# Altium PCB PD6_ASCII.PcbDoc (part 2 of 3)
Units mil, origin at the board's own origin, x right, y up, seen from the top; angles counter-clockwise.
Board outline 8543.31 x 5314.96 mil, 4 copper layers (Top Layer, VBAT Plane, GND Plane, Bottom Layer), stack 62.8 mil thick; 258 components, 142 nets, 690 pads, 87 vias.
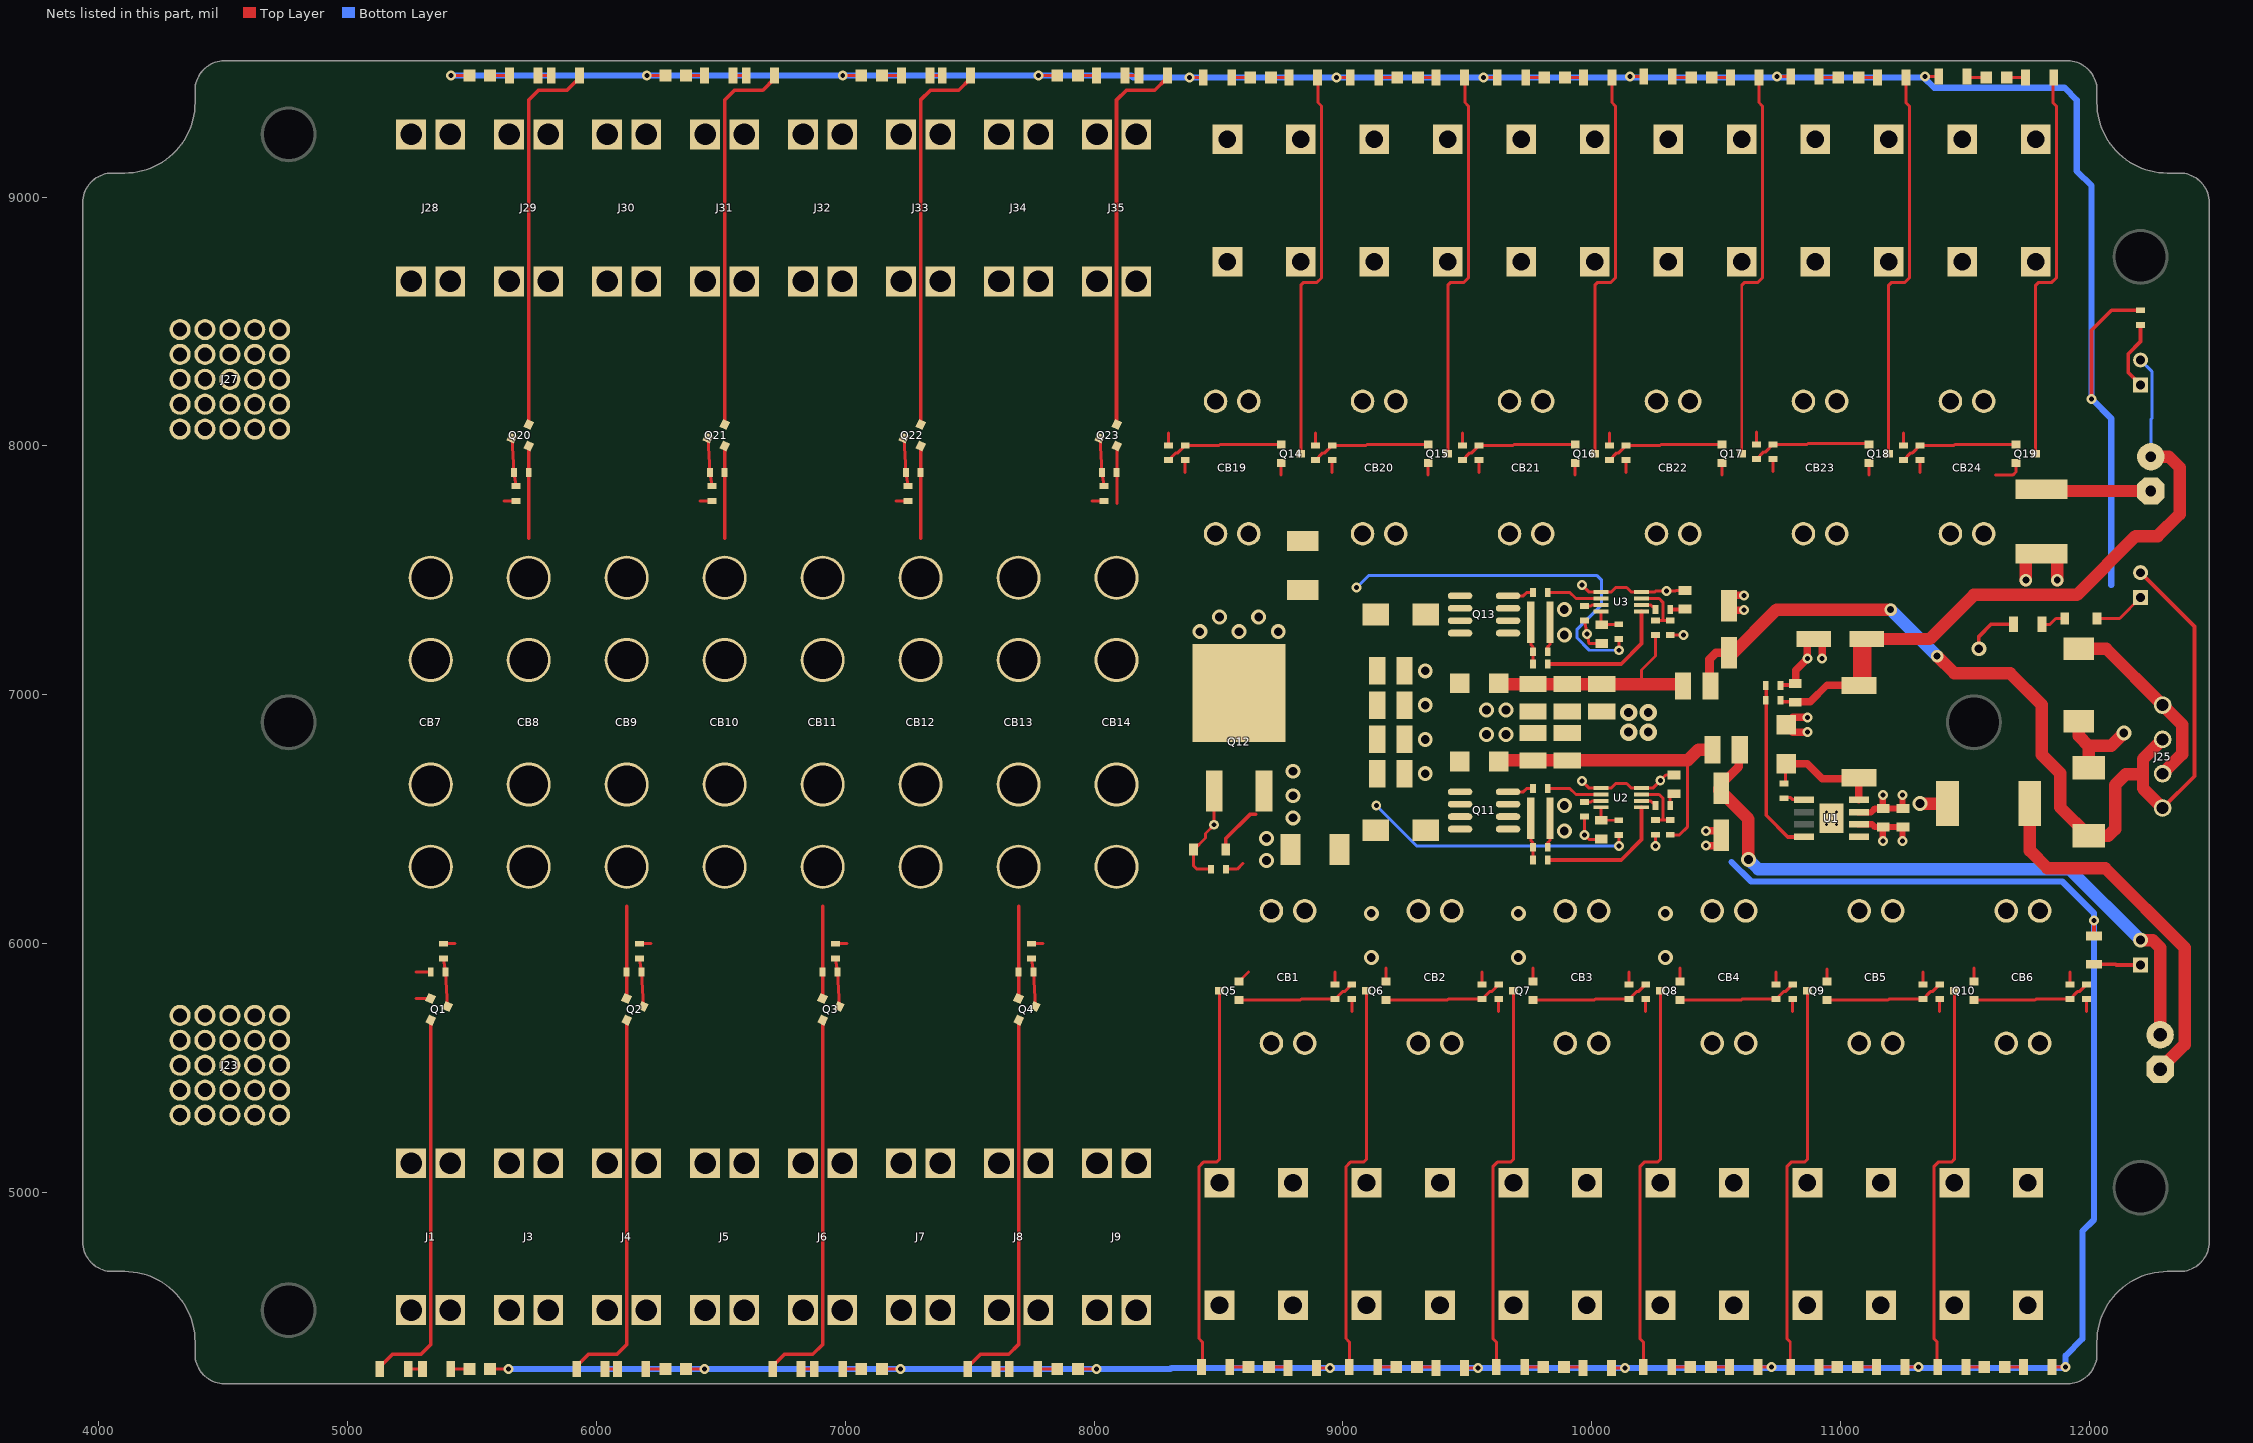
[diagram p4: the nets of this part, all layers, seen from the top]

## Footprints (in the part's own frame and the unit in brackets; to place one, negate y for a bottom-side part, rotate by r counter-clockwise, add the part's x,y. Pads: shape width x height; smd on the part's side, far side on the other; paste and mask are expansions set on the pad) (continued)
"WURTH WE-HC 744314X" [mm] "SMT Power Inductors"
  rect 2.2x2.7 smd: 1(0,2.55) 2(0,-2.55)
  silkscreen extent -3.75,-3.75 3.75,3.75

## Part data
C1 C2: library part "4.7uF 0805 25V X5R", "CERAMIC 4.7uF 25V X5R 0805"
C3 C5 C19: library part "0.01 uF 0603 50V"
C4 C6 C11 C12 C14 C15 C17 C20: "Capacitor"
C7 C8 C9 C10 C13 C16: library part "22uF 1210 25V X5R", "Capacitor"
C18: library part "330µF 6.3V CAN-SMT", "330µF 6.3V ELECT CAN-SMT"
C21 C22: library part "100µF 35V CAN-SMT", "100µF 35V CAN-SMT"
CB1 CB2 CB3 CB4 CB5 CB6 CB19 CB20 CB21 CB22 CB23 CB24: library part "KeyElco 3557-2", "Standard Automotive Blade Fuse Clips & Holder - Edge"
CB7 CB8 CB9 CB10 CB11 CB12 CB13 CB14: library part "KeyElco 3555-2", "\"MAXI\" Automotive Fuse Clip and Holder"
CB15 CB18: library part "Fuse SSQ 15", "FUSE 12A 125V 6125 FAST SSQ"
CB16: library part MF-SM200-2, "PTC 2A /  4A SMT"
CB17: library part MF-MSMF200-2, "PTC 1.1A /  2.2A SMT"
CB25: library part 2920L300/15DR, "PTC 3A /  5A SMT2920"
D1 D2 D3 D4 D5 D6 D7 D8 D9 D10 D18 D19 D20 D21 D22 D23 D24 D25 D26 D27: library part LTST-S220KRKT, "Red 0805 Side Fire 2.0V 20mA 54mCd"
D11 D14 D17: library part LTL-10233W, "T-1 3/4 Green"
D12 D13 D15: "3A Schottky Diode"
D16 D28: library part MMSZ5242BT1G_1, "12V 500mW Zener"
D30: library part SMCJ26A
J1 J4 J6 J8 J29 J31 J33 J35: library part "Wago 745-85X Grey", "Wago 745-85X Grey"
J2 J36: library part "Wago 745-500", "Wago 745-85X End Plate"
J3 J5 J7 J9 J28 J30 J32 J34: library part "Wago 745-85X Blue", "Wago 745-85X Blue"
J10 J49: library part "Wago 745-300", "Wago 745-83X End Plate"
J11 J13 J15 J17 J19 J21 J38 J40 J42 J44 J46 J48: library part "Wago 745-83X Grey", "Wago 745-83X Grey"
J12 J14 J16 J18 J20 J22 J37 J39 J41 J43 J45 J47: library part "Wago 745-83X Blue", "Wago 745-83X Blue"
J23 J27: library part "Wurth M6 PressFit Shank"
J24 J26: library part "WAGO 734-132", "3.5mm Header Protected against Mismating"
J25: "4 position, vertical locking connector with screw flanges, 3.5mm spacing"
L1: library part "WE-HC 4.7-6", "4.7 µH 6 A 20% SMD"
L2: library part MSS1038-183ML_
L3: library part "WE-HC 6.5-6", "6.5 µH 6 A 20% SMD"
L4 L5: library part BRL3225T1R0M, "1uH 1210 2.4A"
Q1 Q2 Q3 Q4 Q5 Q6 Q7 Q8 Q9 Q10 Q14 Q15 Q16 Q17 Q18 Q19 Q20 Q21 Q22 Q23: library part BSS84LT1, "P-Channel MOSFET, -50V, 130mA, 5 Ohm"
Q11: "N-CH 30V 8SOIC"
Q12: library part FDB8441, "N-Channel Powertrench MOSFET, 40V, 80A, 2.5mOhm"
Q13: "N-CH 40V SO8 12.8A"
R32 R46: library part "25 milliohm RL3720 2% 1W", "25 milliohm RL3720 2% 1W"
R82 R83 R84 R85 R86 R87 R88 R89 R90 R91 R92 R93 R94 R95 R96 R97 R98 R99 R100 R101: library part "100k ohm 0603 1%", "100k ohm 0603 1%"
U1: library part TPS5431, "3-A, WIDE INPUT RANGE, STEP-DOWN SWIFT CONVERTER"
U2: "SEPIC Controller"
U3: "Low Side N Switcher Controller - Boost, Flyback, SEPIC"

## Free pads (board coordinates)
  round 225 hole 200: "Mounting Hole"(4763.78,4527.56) "Mounting Hole"(4763.78,6889.76) "Mounting Hole"(4763.78,9251.97) "Mounting Hole"(11535.43,6889.76) "Mounting Hole"(12204.72,5019.69) "Mounting Hole"(12204.72,8759.84)

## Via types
v1: diameter 40, hole 20, Top Layer to Bottom Layer, 47 vias
v2: diameter 60, hole 35, Top Layer to Bottom Layer, 32 vias
v3: diameter 70, hole 35, Top Layer to Bottom Layer, 4 vias
v4: diameter 50, hole 27.99, Top Layer to Bottom Layer, 4 vias

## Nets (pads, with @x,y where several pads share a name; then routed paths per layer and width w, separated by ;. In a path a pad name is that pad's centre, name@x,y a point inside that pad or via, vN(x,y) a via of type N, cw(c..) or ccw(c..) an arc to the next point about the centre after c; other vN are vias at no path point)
5V_OUT: C15.2 C18.+ D17.A J26.2 L2.2 R43.2 | length 2700
  Top Layer w15: R43.2@10755.91,6972.44 10757.87,6972.44 C15.2@10811.02,6972.44
  Top Layer w30: C15.2@10818.9,6972.44 10877.95,6972.44 10944.88,7039.37 L2.2@11070.87,7039.37
  Top Layer w50: L2.2@11070.87,7035.43 11070.87,7037.4 L2.2@11070.87,7039.37 ; C18.+@11104.33,7224.41 11358.27,7224.41 11535.43,7401.57 11948.82,7401.57 12185.04,7637.8 12273.62,7637.8 12362.2,7726.38 12362.2,7913.39 12318.9,7956.69 J26.2@12246.06,7956.69
  Top Layer w75: L2.2@11086.61,7047.24 C18.+@11086.61,7212.6
  Bottom Layer w12: D17.A@12204.72,8345.28 12250,8300 12250,8110 12246.06,8106.06 J26.2@12246.06,7956.69
12_VIN: C7.2 C10.2 CB15.1 L1.2 R34.2 | length 1087.4
  Top Layer w12: v1(10108.27,6391.73) R34.2@10108.27,6437.01
  Bottom Layer w12: v1(9133.86,6555.12) 9297.24,6391.73 v1(10108.27,6391.73)
12V_OUT: C22.+ D11.A J24.2 L5.2 | length 2667.6
  Top Layer w35: C22.+@10505,6625 10512.24,6632.24 10590.55,6710.55 L5.2@10590.55,6779.53
  Top Layer w50: C22.+@10512.76,6617.24 10629.18,6500.82 v2@10629.18,6338.58 ; D11.A@12204.72,6014.57 12253.15,6014.57 12283.46,5984.25 J24.2@12283.46,5633.86
  Bottom Layer w50: v2(10629.92,6338.58) 10669.29,6299.21 11920.08,6299.21 D11.A@12204.72,6014.57
24_VIN: C13.2 C16.2 CB18.1 L3.2 R47.1 | length 1518.8
  Top Layer w12: v1(10108.27,7179.13) R47.1@10108.27,7224.41
  Bottom Layer w12: v1(9055.12,7431.1) 9104.33,7480.31 10019.68,7480.31 10039.37,7460.63 10039.37,7362.2 9940.94,7263.78 9940.94,7228.35 9990.16,7179.13 v1(10108.27,7179.13)
24V_OUT: C21.+ D14.A D30.K J25.1 J25.3 L4.2 | length 4156.3
  Top Layer w15: D14.A@12204.72,7490.94 12421.26,7274.41 12421.26,6673.23 J25.1@12293.31,6545.28
  Top Layer w35: L4.2@10472.44,7023.62 10472.44,7035.43 10472.44,7142.44 10499.29,7169.29 C21.+@10551.18,7169.29
  Top Layer w50: C21.+@10554.19,7154.47 10560.1,7160.37 10742.24,7342.52 v4(11200.79,7342.52) ; v4(11387.8,7155.51) 11456.69,7086.61 11681.1,7086.61 11807.09,6960.63 11807.09,6759.84 11881.89,6685.04 11881.89,6548.23 D30.K@11996.06,6434.06 12075.79,6434.06 12102.36,6460.63 12102.36,6637.8 12145.66,6681.09 12214.57,6681.09 ; J25.1@12293.31,6545.28 12214.57,6624.02 12214.57,6681.09 ; J25.3@12293.31,6820.87 12214.57,6742.13 12214.57,6681.09
  Bottom Layer w50: v4(11200.79,7342.52) v4(11387.8,7155.51)
GND: J1.1 J4.1 J6.1 J8.1 J11.1 J13.1 J15.1 J17.1 J19.1 J21.1 J27.PAD J29.1 J31.1 J33.1 J35.1 J38.1 J40.1 J42.1 J44.1 J46.1 J48.1 Q12.D
  other v2: 8425.2,7253.94 8582.68,7253.94 8740.16,7253.94 8503.94,7312.99 8661.42,7312.99
HIGHCURRENTOUT_1_1: CB8.2 J3.1 R82.2 | length 47.2
  Top Layer w12: R82.2@5385.83,6000 5433.07,6000
HIGHCURRENTOUT_1_2: CB13.2 J34.1 R86.2 | length 47.2
  Top Layer w12: 7992.13,7779.53 R86.2@8039.37,7779.53
HIGHCURRENTOUT_2_1: CB10.2 J5.1 R83.2 | length 47.2
  Top Layer w12: R83.2@6173.23,6000 6220.47,6000
HIGHCURRENTOUT_2_2: CB11.2 J32.1 R87.2 | length 47.2
  Top Layer w12: 7204.72,7779.53 R87.2@7251.97,7779.53
HIGHCURRENTOUT_3_1: CB12.2 J7.1 R84.2 | length 47.2
  Top Layer w12: R84.2@6960.63,6000 7007.87,6000
HIGHCURRENTOUT_3_2: CB9.2 J30.1 R88.2 | length 47.2
  Top Layer w12: 6417.32,7779.53 R88.2@6464.57,7779.53
HIGHCURRENTOUT_4_1: CB14.2 J9.1 R85.2 | length 47.2
  Top Layer w12: R85.2@7748.03,6000 7795.28,6000
HIGHCURRENTOUT_4_2: CB7.2 J28.1 R89.2 | length 47.2
  Top Layer w12: 5629.92,7779.53 R89.2@5677.17,7779.53
LOWCURRENTOUT_1_1: CB1.2 J12.1 R96.2 | length 49.2
  Top Layer w12: 9035.43,5728.35 R96.2@9035.43,5777.56
LOWCURRENTOUT_1_2: CB24.2 J47.1 R90.2 | length 49.2
  Top Layer w12: R90.2@11251.97,8001.97 11251.97,8051.18
LOWCURRENTOUT_2_1: CB2.2 J14.1 R97.2 | length 49.2
  Top Layer w12: 9625.98,5728.35 R97.2@9625.98,5777.56
LOWCURRENTOUT_2_2: CB23.2 J45.1 R91.2 | length 98.4
  Top Layer w12: R91.2@10661.42,8001.97 R91.2@10661.42,8005.91 ; 10661.42,8051.18 R91.2@10661.42,8005.91 ; 10661.42,8055.12 R91.2@10661.42,8005.91
LOWCURRENTOUT_3_1: CB3.2 J16.1 R98.2 | length 49.2
  Top Layer w12: 10216.54,5728.35 R98.2@10216.54,5777.56
LOWCURRENTOUT_3_2: CB22.2 J43.1 R92.2 | length 49.2
  Top Layer w12: R92.2@10070.87,8001.97 10070.87,8051.18
LOWCURRENTOUT_4_1: CB4.2 J18.1 R99.2 | length 49.2
  Top Layer w12: 10807.09,5728.35 R99.2@10807.09,5777.56
LOWCURRENTOUT_4_2: CB21.2 J41.1 R93.2 | length 49.2
  Top Layer w12: R93.2@9480.32,8001.97 9480.32,8051.18
LOWCURRENTOUT_5_1: CB5.2 J20.1 R100.2 | length 49.2
  Top Layer w12: 11397.64,5728.35 R100.2@11397.64,5777.56
LOWCURRENTOUT_5_2: CB20.2 J39.1 R94.2 | length 49.2
  Top Layer w12: R94.2@8889.76,8001.97 8889.76,8051.18
LOWCURRENTOUT_6_1: CB6.2 J22.1 R101.2 | length 49.2
  Top Layer w12: 11988.19,5728.35 R101.2@11988.19,5777.56
LOWCURRENTOUT_6_2: CB19.2 J37.1 R95.2 | length 49.2
  Top Layer w12: R95.2@8299.21,8001.97 8299.21,8051.18
NetC3_2: C3.2 Q11.S R32.2 R33.2 | length 171
  Top Layer w12: R32.2@9754.92,6503.94 9754.92,6414.37 9763.78,6405.51 C3.2@9763.78,6387.8 R33.2@9763.78,6336.61
NetC4_2: C4.2 R34.1 U2.8 | length 114.2
  Top Layer w12: C4.2@10036.42,6500.98 U2.8@10036.42,6548.23 ; C4.2@10041.34,6496.06 R34.1@10108.27,6496.06
NetC5_1: C5.1 U1.1 | length 89.9
  Top Layer w12: C5.1@10767.72,6586.61 10771.65,6586.61 10799.21,6586.61 10807.09,6578.74 10852.83,6578.74 U1.1@10854.33,6578.74
NetC5_2: C5.2 D13.K L2.1 U1.8 | length 472.9
  Top Layer w12: C5.2@10777.56,6643.7 D13.K@10777.56,6712.6
  Top Layer w25: D13.K@10777.56,6722.44 D13.K@10781.5,6722.44
  Top Layer w30: D13.K@10781.5,6722.44 10866.14,6722.44 10925.2,6663.39 11072.83,6663.39 U1.8@11072.83,6579.13
NetC6_2: C6.2 R37.1 | length 49.9
  Top Layer w12: R37.1@10314.96,6555.12 10314.96,6602.6 10314.96,6604.96 C6.2@10315,6605
NetC8_2: C8.2 C9.2 D12.K L5.1 R40.2 | length 1217
  Top Layer w12: R40.2@10314.8,6437.64 10352.64,6437.64 10385,6470 10385,6736.34
  Top Layer w50: D12.K@9625.98,6736.34 C8.2@9763.78,6736.34 C9.2@9901.57,6736.34 10385,6736.34 10428.66,6780 L5.1@10475,6780
NetC17_2: C17.2 R47.2 U3.8 | length 114.2
  Top Layer w12: C17.2@10036.42,7288.39 U3.8@10036.42,7335.63 ; C17.2@10041.34,7283.46 R47.2@10108.27,7283.46
NetC19_2: C19.2 Q13.S R44.2 R46.2 | length 171
  Top Layer w12: R46.2@9754.92,7291.34 9754.92,7201.77 9763.78,7192.91 C19.2@9763.78,7173.23 R44.2@9763.78,7124.02
NetC20_2: C20.2 R49.1 | length 57.1
  Top Layer w15: R49.1@10314.96,7342.52 C20.2@10372.05,7342.52
NetCB16_2: CB16.2 J24.1 | length 1501.4
  Top Layer w50: CB16.2@11759.84,6562.99 11759.84,6374.02 11830.71,6303.15 12062.99,6303.15 12381.89,5984.25 12381.89,5594.49 J24.1@12283.46,5496.06
NetCB17_2: CB17.2 J25.2 J25.4 | length 771.2
  Top Layer w50: CB17.2@11956.69,7185.04 12066.93,7185.04 J25.4@12293.31,6958.66 12372.05,6879.92 12372.05,6761.81 J25.2@12293.31,6683.07
NetCB25_2: CB25.2 J26.1 | length 442.2
  Top Layer w50: CB25.2@11807.09,7826.77 11814.96,7818.9 J26.1@12246.06,7818.9
NetD1_A: D1.A R2.2 | length 84.6
  Top Layer w12: R2.2@5411.42,4291.34 R2.2@5415.35,4291.34 D1.A@5496.06,4291.34
NetD2_A: D2.A R4.2 | length 84.6
  Top Layer w12: R4.2@6198.82,4291.34 D2.A@6283.46,4291.34
NetD3_A: D3.A R6.2 | length 84.6
  Top Layer w12: R6.2@6986.22,4291.34 R6.2@6990.16,4291.34 D3.A@7070.87,4291.34
NetD4_A: D4.A R8.2 | length 84.6
  Top Layer w12: R8.2@7773.62,4291.34 D4.A@7858.27,4291.34
NetD5_A: D5.A R9.2 | length 76.8
  Top Layer w12: R9.2@8549.21,4299.21 D5.A@8625.98,4299.21
NetD5_K: D5.K R10.1 | length 82.7
  Top Layer w12: D5.K@8696.85,4299.21 R10.1@8779.53,4299.21
NetD6_A: D6.A R11.2 | length 80.7
  Top Layer w12: R11.2@9139.76,4299.21 D6.A@9220.47,4299.21
NetD6_K: D6.K R12.1 | length 78.7
  Top Layer w12: D6.K@9291.34,4299.21 R12.1@9370.08,4299.21
NetD7_A: D7.A R13.2 | length 80.7
  Top Layer w12: R13.2@9730.32,4299.21 D7.A@9811.02,4299.21
NetD7_K: D7.K R14.1 | length 78.7
  Top Layer w12: D7.K@9881.89,4299.21 R14.1@9960.63,4299.21
NetD8_A: D8.A R15.2 | length 80.7
  Top Layer w12: R15.2@10320.87,4299.21 D8.A@10401.57,4299.21
NetD8_K: D8.K R16.1 | length 78.7
  Top Layer w12: D8.K@10472.44,4299.21 R16.1@10551.18,4299.21
NetD9_A: D9.A R17.2 | length 80.7
  Top Layer w12: R17.2@10911.42,4299.21 R17.2@10913.39,4299.21 D9.A@10992.13,4299.21
NetD9_K: D9.K R18.1 | length 78.7
  Top Layer w12: D9.K@11062.99,4299.21 R18.1@11141.73,4299.21
NetD10_A: D10.A R19.2 | length 80.7
  Top Layer w12: R19.2@11501.97,4299.21 R19.2@11503.94,4299.21 D10.A@11582.68,4299.21
NetD10_K: D10.K R20.1 | length 78.7
  Top Layer w12: D10.K@11653.54,4299.21 R20.1@11732.28,4299.21
NetD11_K: D11.K R21.2 | length 188.1
  Top Layer w15: R21.2@12017.72,5917.32 12104.33,5917.32 12107.09,5914.57 D11.K@12204.72,5914.57
NetD12_A: D12.A L1.1 Q11.D
NetD14_K: D14.K D16.K | length 210.4
  Top Layer w12: D16.K@12029.06,7307.09 12120.87,7307.09 D14.K@12204.72,7390.94
NetD15_A: D15.A L3.1 Q13.D
NetD16_A: D16.A R35.2 | length 100.8
  Top Layer w12: R35.2@11809.06,7283.46 11840.55,7283.46 11864.17,7307.09 D16.A@11900.08,7307.09
NetD17_K: D17.K R61.2 | length 282.1
  Top Layer w15: D17.K@12204.72,8245.28 12155,8295 12155,8370 12204.72,8419.72 R61.2@12204.72,8486.22
NetD18_A: D18.A R62.2 | length 84.6
  Top Layer w12: D18.A@5566.93,9488.19 R62.2@5651.57,9488.19
NetD19_A: D19.A R64.2 | length 84.6
  Top Layer w12: D19.A@6354.33,9488.19 R64.2@6435.04,9488.19 R64.2@6438.98,9488.19
NetD20_A: D20.A R66.2 | length 84.6
  Top Layer w12: D20.A@7141.73,9488.19 R66.2@7226.38,9488.19
NetD21_A: D21.A R68.2 | length 84.6
  Top Layer w12: D21.A@7929.13,9488.19 R68.2@8009.84,9488.19 R68.2@8013.78,9488.19
NetD22_A: D22.A R71.2 | length 80.7
  Top Layer w12: D22.A@8704.72,9480.32 R71.2@8783.46,9480.31 R71.2@8785.43,9480.32
NetD22_K: D22.K R70.1 | length 78.7
  Top Layer w12: R70.1@8555.12,9480.32 D22.K@8633.86,9480.32
NetD23_A: D23.A R73.2 | length 80.7
  Top Layer w12: D23.A@9295.28,9480.32 R73.2@9374.02,9480.31 R73.2@9375.98,9480.32
NetD23_K: D23.K R72.1 | length 78.7
  Top Layer w12: R72.1@9145.67,9480.32 D23.K@9224.41,9480.32
NetD24_A: D24.A R75.2 | length 80.7
  Top Layer w12: D24.A@9885.83,9480.32 R75.2@9966.54,9480.31
NetD24_K: D24.K R74.1 | length 78.7
  Top Layer w12: R74.1@9736.22,9480.32 D24.K@9814.96,9480.32
NetD25_A: D25.A R77.2 | length 80.7
  Top Layer w12: D25.A@10476.38,9480.32 R77.2@10557.09,9480.32
NetD25_K: D25.K R76.1 | length 78.7
  Top Layer w12: R76.1@10326.77,9480.32 D25.K@10405.51,9480.32
NetD26_A: D26.A R79.2 | length 80.7
  Top Layer w12: D26.A@11066.93,9480.32 R79.2@11147.64,9480.31
NetD26_K: D26.K R78.1 | length 78.7
  Top Layer w12: R78.1@10917.32,9480.32 D26.K@10996.06,9480.32
NetD27_A: D27.A R81.2 | length 76.8
  Top Layer w12: D27.A@11661.42,9480.32 R81.2@11738.19,9480.32
NetD27_K: D27.K R80.1 | length 82.7
  Top Layer w12: R80.1@11507.87,9480.32 D27.K@11590.55,9480.32
NetD28_K: D28.K Q12.G R102.1 | length 411.8
  Top Layer w12: R102.1@8470.47,6299.21 8413.39,6299.21 8400.08,6312.52 D28.K@8400.08,6377.95 8447.32,6425.2 8447.32,6442.6 v1(8482.68,6477.95) Q12.G@8482.68,6614.17
NetQ1_D: Q1.D R1.1 | length 1539.6
  Top Layer w15: R1.1@5133.86,4303.15 5181.1,4350.39 5295.28,4350.39 5334.65,4389.76 Q1.D@5334.65,5692.67
NetQ1_G: Q1.G R22.2 R82.1 | length 193.5
  Top Layer w12: R82.1@5385.83,5940.94 R22.2@5393.7,5885.83 Q1.G@5401.82,5748.22
NetQ2_D: Q2.D R3.1 | length 1539.6
  Top Layer w15: R3.1@5921.26,4303.15 5968.5,4350.39 6082.68,4350.39 6122.05,4389.76 Q2.D@6122.05,5692.67
NetQ2_G: Q2.G R23.2 R83.1 | length 193.5
  Top Layer w12: R83.1@6173.23,5940.94 R23.2@6181.1,5885.83 Q2.G@6189.22,5748.22
NetQ3_D: Q3.D R5.1 | length 1539.6
  Top Layer w15: R5.1@6708.66,4303.15 6755.91,4350.39 6870.08,4350.39 6909.45,4389.76 Q3.D@6909.45,5692.67
NetQ3_G: Q3.G R24.2 R84.1 | length 193.5
  Top Layer w12: R84.1@6960.63,5940.94 R24.2@6968.5,5885.83 Q3.G@6976.62,5748.22
NetQ4_D: Q4.D R7.1 | length 1539.6
  Top Layer w15: R7.1@7496.06,4303.15 7543.31,4350.39 7657.48,4350.39 7696.85,4389.76 Q4.D@7696.85,5692.67
NetQ4_G: Q4.G R25.2 R85.1 | length 193.5
  Top Layer w12: R85.1@7748.03,5940.94 R25.2@7755.91,5885.83 Q4.G@7764.02,5748.22
NetQ5_D: Q5.D R9.1 | length 1582.9
  Top Layer w12: R9.1@8431.1,4299.21 8435.04,4299.21 8435.04,4399.61 8421.26,4413.39 8421.26,5104.33 8438.98,5122.05 8492.13,5122.05 8503.94,5133.86 Q5.D@8503.94,5807.09
NetQ5_G: Q5.G R26.2 R96.1 | length 478.8
  Top Layer w12: Q5.G@8582.68,5773.62 8828.74,5773.62 8832.68,5777.56 R26.2@8968.5,5777.56 8998.03,5807.09 9005.91,5807.09 R96.1@9035.43,5836.61
NetQ6_D: Q6.D R11.1 | length 1579
  Top Layer w12: R11.1@9025.59,4299.21 9025.59,4399.61 9011.81,4413.39 9011.81,5104.33 9029.53,5122.05 9082.68,5122.05 9094.49,5133.86 Q6.D@9094.49,5807.09
NetQ6_G: Q6.G R27.2 R97.1 | length 478.8
  Top Layer w12: Q6.G@9173.23,5773.62 9419.29,5773.62 9423.23,5777.56 R27.2@9559.06,5777.56 9588.58,5807.09 9596.46,5807.09 R97.1@9625.98,5836.61
NetQ7_D: Q7.D R13.1 | length 1579
  Top Layer w12: R13.1@9616.14,4299.21 9616.14,4399.61 9602.36,4413.39 9602.36,5104.33 9620.08,5122.05 9673.23,5122.05 9685.04,5133.86 Q7.D@9685.04,5807.09
NetQ7_G: Q7.G R28.2 R98.1 | length 478.8
  Top Layer w12: Q7.G@9763.78,5773.62 10009.84,5773.62 10013.78,5777.56 R28.2@10149.61,5777.56 10179.13,5807.09 10187.01,5807.09 R98.1@10216.54,5836.61
NetQ8_D: Q8.D R15.1 | length 1579
  Top Layer w12: R15.1@10206.69,4299.21 10206.69,4399.61 10192.91,4413.39 10192.91,5104.33 10210.63,5122.05 10263.78,5122.05 10275.59,5133.86 Q8.D@10275.59,5807.09
NetQ8_G: Q8.G R29.2 R99.1 | length 478.8
  Top Layer w12: Q8.G@10354.33,5773.62 10600.39,5773.62 10604.33,5777.56 R29.2@10740.16,5777.56 10769.68,5807.09 10777.56,5807.09 R99.1@10807.09,5836.61
NetQ9_D: Q9.D R17.1 | length 1579
  Top Layer w12: R17.1@10797.24,4299.21 10797.24,4399.61 10783.46,4413.39 10783.46,5104.33 10801.18,5122.05 10854.33,5122.05 10866.14,5133.86 Q9.D@10866.14,5807.09
NetQ9_G: Q9.G R30.2 R100.1 | length 478.8
  Top Layer w12: Q9.G@10944.88,5773.62 11190.94,5773.62 11194.88,5777.56 R30.2@11330.71,5777.56 11360.24,5807.09 11368.11,5807.09 R100.1@11397.64,5836.61
NetQ10_D: Q10.D R19.1 | length 1579
  Top Layer w12: R19.1@11387.8,4299.21 11387.8,4399.61 11374.02,4413.39 11374.02,5104.33 11391.73,5122.05 11444.88,5122.05 11456.69,5133.86 Q10.D@11456.69,5807.09
NetQ10_G: Q10.G R31.2 R101.1 | length 478.8
  Top Layer w12: Q10.G@11535.43,5773.62 11781.5,5773.62 11785.43,5777.56 R31.2@11921.26,5777.56 11950.79,5807.09 11958.66,5807.09 R101.1@11988.19,5836.61
NetQ11_G: Q11.G R38.2 | length 106
  Top Layer w12: Q11.G@9663.39,6610.43 9724.61,6610.43 9738.19,6624.02 R38.2@9763.78,6624.02
NetQ13_G: Q13.G R50.2 | length 106
  Top Layer w12: Q13.G@9663.39,7397.83 9724.61,7397.83 9738.19,7411.42 R50.2@9763.78,7411.42
NetQ14_D: Q14.D R71.1 | length 1579
  Top Layer w12: Q14.D@8830.71,7972.44 8830.71,8645.67 8842.52,8657.48 8895.67,8657.48 8913.39,8675.2 8913.39,9366.14 8899.61,9379.92 R71.1@8899.61,9480.31
NetQ14_G: Q14.G R55.2 R95.1 | length 478.8
  Top Layer w12: R95.1@8299.21,7942.91 8328.74,7972.44 8336.61,7972.44 R55.2@8366.14,8001.97 8501.97,8001.97 8505.91,8005.91 Q14.G@8751.97,8005.91
NetQ15_D: Q15.D R73.1 | length 1579
  Top Layer w12: Q15.D@9421.26,7972.44 9421.26,8645.67 9433.07,8657.48 9486.22,8657.48 9503.94,8675.2 9503.94,9366.14 9490.16,9379.92 R73.1@9490.16,9480.31
NetQ15_G: Q15.G R56.2 R94.1 | length 478.8
  Top Layer w12: R94.1@8889.76,7942.91 8919.29,7972.44 8927.17,7972.44 R56.2@8956.69,8001.97 9092.52,8001.97 9096.46,8005.91 Q15.G@9342.52,8005.91
NetQ16_D: Q16.D R75.1 | length 1579
  Top Layer w12: Q16.D@10011.81,7972.44 10011.81,8645.67 10023.62,8657.48 10076.77,8657.48 10094.49,8675.2 10094.49,9366.14 10080.71,9379.92 R75.1@10080.71,9480.31
NetQ16_G: Q16.G R57.2 R93.1 | length 478.8
  Top Layer w12: R93.1@9480.32,7942.91 9509.84,7972.44 9517.72,7972.44 R57.2@9547.24,8001.97 9683.07,8001.97 9687.01,8005.91 Q16.G@9933.07,8005.91
NetQ17_D: Q17.D R77.1 | length 1579
  Top Layer w12: Q17.D@10602.36,7972.44 10602.36,8645.67 10614.17,8657.48 10667.32,8657.48 10685.04,8675.2 10685.04,9366.14 10671.26,9379.92 R77.1@10671.26,9480.32
NetQ17_G: Q17.G R58.2 R92.1 | length 478.8
  Top Layer w12: R92.1@10070.87,7942.91 10100.39,7972.44 10108.27,7972.44 R58.2@10137.8,8001.97 10273.62,8001.97 10277.56,8005.91 Q17.G@10523.62,8005.91
NetQ18_D: Q18.D R79.1 | length 1579
  Top Layer w12: Q18.D@11192.91,7972.44 11192.91,8645.67 11204.72,8657.48 11257.87,8657.48 11275.59,8675.2 11275.59,9366.14 11261.81,9379.92 R79.1@11261.81,9480.31
NetQ18_G: Q18.G R59.2 R91.1 | length 478.8
  Top Layer w12: R91.1@10661.42,7946.85 10690.94,7976.38 10698.82,7976.38 R59.2@10728.35,8005.91 10864.17,8005.91 10868.11,8009.84 Q18.G@11114.17,8009.84
NetQ19_D: Q19.D R81.1 | length 1582.9
  Top Layer w12: Q19.D@11783.46,7972.44 11783.46,8645.67 11795.28,8657.48 11848.43,8657.48 11866.14,8675.2 11866.14,9366.14 11852.36,9379.92 11852.36,9480.31 R81.1@11856.3,9480.32
NetQ19_G: Q19.G R60.2 R90.1 | length 478.8
  Top Layer w12: R90.1@11251.97,7942.91 11281.5,7972.44 11289.37,7972.44 R60.2@11318.9,8001.97 11454.72,8001.97 11458.66,8005.91 Q19.G@11704.72,8005.91
NetQ20_D: Q20.D R63.1 | length 1539.6
  Top Layer w15: Q20.D@5728.35,8086.86 5728.35,9389.76 5767.72,9429.13 5881.89,9429.13 R63.1@5929.13,9476.38
NetQ20_G: Q20.G R51.2 R89.1 | length 193.5
  Top Layer w12: Q20.G@5661.17,8031.31 R51.2@5669.29,7893.7 R89.1@5677.17,7838.58
NetQ21_D: Q21.D R65.1 | length 1539.6
  Top Layer w15: Q21.D@6515.75,8086.86 6515.75,9389.76 6555.12,9429.13 6669.29,9429.13 R65.1@6716.54,9476.38
NetQ21_G: Q21.G R52.2 R88.1 | length 193.5
  Top Layer w12: Q21.G@6448.57,8031.31 R52.2@6456.69,7893.7 R88.1@6464.57,7838.58
NetQ22_D: Q22.D R67.1 | length 1539.6
  Top Layer w15: Q22.D@7303.15,8086.86 7303.15,9389.76 7342.52,9429.13 7456.69,9429.13 R67.1@7503.94,9476.38
NetQ22_G: Q22.G R53.2 R87.1 | length 193.5
  Top Layer w12: Q22.G@7235.98,8031.31 R53.2@7244.09,7893.7 R87.1@7251.97,7838.58
NetQ23_D: Q23.D R69.1 | length 1539.6
  Top Layer w15: Q23.D@8090.55,8086.86 8090.55,9389.76 8129.92,9429.13 8244.09,9429.13 R69.1@8291.34,9476.38
NetQ23_G: Q23.G R54.2 R86.1 | length 193.5
  Top Layer w12: Q23.G@8023.38,8031.31 R54.2@8031.5,7893.7 R86.1@8039.37,7838.58
NetR1_2: R1.2 R2.1 | length 53.1
  Top Layer w12: R1.2@5244.09,4291.34 R2.1@5297.24,4291.34
NetR3_2: R3.2 R4.1 | length 53.1
  Top Layer w12: R3.2@6031.5,4291.34 R3.2@6035.43,4291.34 R4.1@6084.65,4291.34
NetR5_2: R5.2 R6.1 | length 53.1
  Top Layer w12: R5.2@6818.9,4291.34 R5.2@6822.83,4291.34 R6.1@6872.05,4291.34
NetR7_2: R7.2 R8.1 | length 53.1
  Top Layer w12: R7.2@7606.3,4291.34 R8.1@7659.45,4291.34
NetR33_1: R33.1 U2.1 | length 540.7
  Top Layer w15: R33.1@9822.83,6336.61 10118.11,6336.61 10199.8,6418.31 U2.1@10199.8,6548.23
NetR36_2: R36.2 U2.7 | length 67.6
  Top Layer w12: R36.2@9970.47,6569.88 9997.05,6569.88 10000.98,6573.82 U2.7@10036.42,6573.82
NetR37_2: R37.2 U2.2 | length 63.8
  Top Layer w12: U2.2@10199.8,6573.82 10237.2,6573.82 R37.2@10255.91,6555.12
NetR38_1: R38.1 U2.6 | length 223.8
  Top Layer w12: R38.1@9822.83,6624.02 9911.42,6624.02 9936.02,6599.41 U2.6@10036.42,6599.41
NetR39_2: R39.2 R40.1 U2.3 | length 238.5
  Top Layer w12: U2.3@10199.8,6599.41 10270.59,6599.41 10285,6585 10285,6496.69 ; R39.2@10255.75,6496.69 10285,6496.69 ; R40.1@10314.8,6496.69 10285,6496.69
NetR41_1: R41.1 R42.2 U3.3 | length 223.6
  Top Layer w12: U3.3@10199.8,7386.81 10270.67,7386.81 10285.43,7372.05 10285.43,7299.21 ; R41.1@10255.91,7299.21 10285.43,7299.21 ; R42.2@10314.96,7299.21 10285.43,7299.21
NetR43_1: R43.1 R45.2 U1.4 | length 709.1
  Top Layer w15: R45.2@10700.79,7035.43 10700.79,6978.35 10700.79,6515.75 10787.4,6429.13 U1.4@10852.83,6429.13 U1.4@10854.33,6429.13
NetR44_1: R44.1 U3.1 | length 540.7
  Top Layer w15: R44.1@9822.83,7124.02 10118.11,7124.02 10199.8,7205.71 U3.1@10199.8,7335.63
NetR48_2: R48.2 U3.7 | length 67.6
  Top Layer w12: R48.2@9970.47,7357.28 9997.05,7357.28 10000.98,7361.22 U3.7@10036.42,7361.22
NetR49_2: R49.2 U3.2 | length 63.8
  Top Layer w12: U3.2@10199.8,7361.22 10237.2,7361.22 R49.2@10255.91,7342.52
NetR50_1: R50.1 U3.6 | length 223.8
  Top Layer w12: R50.1@9822.83,7411.42 9911.42,7411.42 9936.02,7386.81 U3.6@10036.42,7386.81
NetR62_1: R62.1 R63.2 | length 53.1
  Top Layer w12: R62.1@5765.75,9488.19 R63.2@5818.9,9488.19
NetR64_1: R64.1 R65.2 | length 53.1
  Top Layer w12: R64.1@6553.15,9488.19 R65.2@6602.36,9488.19 R65.2@6606.3,9488.19
NetR66_1: R66.1 R67.2 | length 53.1
  Top Layer w12: R66.1@7340.55,9488.19 R67.2@7389.76,9488.19 R67.2@7393.7,9488.19
NetR68_1: R68.1 R69.2 | length 53.1
  Top Layer w12: R68.1@8127.95,9488.19 R69.2@8181.1,9488.19
NetU1_5: U1.5
"OUTPUT VOLTAGE": C11.2 C12.2 C14.2 D15.K L4.1 R41.2 | length 954.9
  Top Layer w12: 10200,7043.19 10200,7100 10255.91,7155.91 R41.2@10255.91,7240.16
  Top Layer w50: D15.K@9625.98,7043.19 C14.2@9763.78,7043.19 C11.2@9901.57,7043.19 C12.2@10039.37,7043.19 10200,7043.19 10358.19,7043.19 10358.35,7043.35 L4.1@10360,7045
PSGND: C1.1 C2.1 C3.1 C4.1 C6.1 C7.1 C8.1 C9.1 C10.1 C11.1 C12.1 C13.1 C14.1 C15.1 C16.1 C17.1 C18.- C19.1 C20.1 C21.- C22.- CB16.1 CB17.1 CB25.1 D1.K D2.K D3.K D4.K D13.A D18.K D19.K D20.K D21.K D28.A D30.A Q12.S R10.2 R12.2 R14.2 R16.2 R18.2 R20.2 R21.1 R32.1 R35.1 R36.1 R39.1 R42.1 R45.1 R46.1 R48.1 R61.1 R70.2 R72.2 R74.2 R76.2 R78.2 R80.2 U1.6 U1.PAD U2.4 U2.5 U3.4 U3.5 | length 27983.5
  Top Layer w12: v1(5415.35,9488.19) D18.K@5490.16,9488.19 D18.K@5496.06,9488.19 ; D1.K@5566.93,4291.34 D1.K@5572.83,4291.34 v1(5647.64,4291.34) ; v1(6202.76,9488.19) D19.K@6277.56,9488.19 D19.K@6283.46,9488.19 ; D2.K@6354.33,4291.34 D2.K@6360.24,4291.34 v1(6435.04,4291.34) ; v1(6990.16,9488.19) D20.K@7064.96,9488.19 D20.K@7070.87,9488.19 ; D3.K@7141.73,4291.34 D3.K@7147.64,4291.34 v1(7222.44,4291.34) ; v1(7777.56,9488.19) D21.K@7852.36,9488.19 D21.K@7858.27,9488.19 ; D4.K@7929.13,4291.34 D4.K@7935.04,4291.34 v1(8009.84,4291.34) ; v1(8383.86,9480.32) R70.2@8437.01,9480.32 ; R70.2@8437.01,9488.19 R70.2@8437.01,9480.32 ; R70.2@8438.98,9480.31 R70.2@8437.01,9480.32 ; R10.2@8893.7,4295.28 R10.2@8897.64,4295.28 ; R10.2@8897.64,4287.4 R10.2@8897.64,4295.28 ; v1(8948.82,4295.28) R10.2@8897.64,4295.28 ; v1(8974.41,9480.31) R72.2@9027.56,9480.32 ; R72.2@9027.56,9488.19 R72.2@9027.56,9480.32 ; R72.2@9029.53,9480.31 R72.2@9027.56,9480.32 ; R12.2@9488.19,4287.4 R12.2@9488.19,4295.28 v1(9543.31,4295.28) ; v1(9564.96,9480.32) R74.2@9618.11,9480.32 ; R74.2@9618.11,9488.19 R74.2@9618.11,9480.32 ; R74.2@9620.08,9480.32 R74.2@9618.11,9480.32 ; C3.1@9822.83,6385.83 C3.1@9822.83,6387.8 9822.83,6405.51 9831.69,6414.37 R32.1@9831.69,6503.94 ; C19.1@9822.83,7173.23 9822.83,7192.91 9831.69,7201.77 R46.1@9831.69,7291.34 ; v1(9960.63,6653.54) 9989.17,6625 U2.5@10036.42,6625 10077.26,6625 10095.96,6643.7 10140.26,6643.7 10158.96,6625 U2.4@10199.8,6625 10245,6625 v1(10275,6655) 10297.4,6677.4 C6.1@10330,6677.4 ; v1(9960.63,7440.94) 9989.17,7412.4 U3.5@10036.42,7412.4 10077.26,7412.4 10095.96,7431.1 10140.26,7431.1 10158.96,7412.4 U3.4@10199.8,7412.4 10251.97,7412.4 10255.91,7416.34 v1(10300.2,7416.34) 10334.65,7416.34 10337.6,7419.29 C20.1@10374.02,7419.29 ; R36.1@9970.47,6510.83 v1(9970.47,6437.01) 9988.19,6419.29 10037.4,6419.29 C4.1@10039.37,6419.29 ; R48.1@9970.47,7298.23 v1(9980.32,7244.09) 9988.19,7206.69 C17.1@10039.37,7206.69 ; R14.2@10078.74,4287.4 R14.2@10078.74,4295.28 v1(10133.86,4295.28) ; v1(10153.54,9484.25) R76.2@10208.66,9484.25 R76.2@10208.66,9492.13 ; v1(10255.75,6392.36) R39.1@10255.75,6437.64 ; R42.1@10314.96,7240.16 v1(10369.09,7240.16) ; R16.2@10667.32,4299.21 R16.2@10669.29,4299.21 ; R16.2@10669.29,4291.34 R16.2@10669.29,4299.21 ; v1(10722.44,4299.21) R16.2@10669.29,4299.21 ; v1(10744.09,9484.25) R78.2@10799.21,9484.25 R78.2@10799.21,9492.13 ; R18.2@11257.87,4299.21 R18.2@11259.84,4299.21 ; R18.2@11259.84,4291.34 R18.2@11259.84,4299.21 ; v1(11312.99,4299.21) R18.2@11259.84,4299.21 ; v1(11338.58,9484.25) R80.2@11389.76,9484.25 ; R80.2@11389.76,9492.13 R80.2@11389.76,9484.25 ; R80.2@11393.7,9484.25 R80.2@11389.76,9484.25 ; R20.2@11848.43,4299.21 R20.2@11850.39,4299.21 ; R20.2@11850.39,4291.34 R20.2@11850.39,4299.21 ; v1(11903.54,4299.21) R20.2@11850.39,4299.21
  Top Layer w15: D28.A@8529.06,6377.95 8529.06,6422.49 8626.25,6519.69 8649.61,6519.69 ; R45.1@10759.84,7039.37 C15.1@10803.15,7039.37 ; v2(11555.12,7185.04) 11555.12,7234.25 11604.33,7283.46 R35.1@11694.88,7283.46 ; v1(12007.87,8188.98) 12007.87,8464.57 12088.58,8545.28 R61.1@12204.72,8545.28 ; R21.1@12017.72,6031.5 v1(12017.72,6092.52)
  Top Layer w25: U1.6@11070.87,6480.31 11072.83,6480.31 11125.98,6480.31 11137.8,6468.5 C1.1@11171.26,6468.5 11248.03,6468.5 v1(11248.03,6413.39) ; v1(11169.29,6413.39) C1.1@11169.29,6468.5
  Top Layer w30: v1(10458.86,6394.25) 10517.91,6394.25 C22.-@10533.68,6410.02 ; v1(10458.86,6453.31) 10517.91,6453.31 10527.85,6443.37 C22.-@10533.76,6437.46 ; C21.-@10553.27,7340.47 v1(10612.32,7340.47) ; C21.-@10553.27,7399.53 v1(10612.32,7399.53) ; D13.A@10787.4,6870.08 10807.09,6850.39 v1(10866.14,6850.39) ; D13.A@10787.4,6889.76 10807.09,6909.45 v1(10866.14,6909.45) ; C15.1@10818.9,7047.24 10818.9,7098.43 v1(10866.14,7145.67) C18.-@10866.14,7204.72 ; v1(10925.2,7145.67) C18.-@10925.2,7204.72
  Top Layer w50: v2(11318.9,6562.99) CB16.1@11429.13,6562.99 ; CB25.1@11742.13,7568.9 11744.09,7566.93 v4(11744.09,7460.63) ; v4(11870.08,7460.63) 11870.08,7566.93 CB25.1@11870.08,7568.9 ; CB17.1@11956.69,6893.7 11956.69,6834.65 11996.06,6795.28 ; D30.A@11996.06,6707.68 11996.06,6795.28 ; v2(12137.8,6846.46) 12086.61,6795.28 11996.06,6795.28
  Bottom Layer w25: v1(5415.35,9488.19) v1(6202.76,9488.19) v1(6990.16,9488.19) v1(7777.56,9488.19) 8149.61,9488.19 8157.48,9480.32 v1(8383.86,9480.32) ; v1(5647.64,4291.34) v1(6435.04,4291.34) v1(7222.44,4291.34) v1(8009.84,4291.34) 8307.09,4291.34 8311.02,4295.28 v1(8948.82,4295.28) v1(9543.31,4295.28) v1(10133.86,4295.28) ; 10561.02,6328.74 10639.76,6250 11889.76,6250 12017.72,6122.05 v1(12017.72,6092.52) 12017.72,4891.73 11970.96,4844.98 11970.96,4411.91 11903.54,4344.49 v1(11903.54,4299.21) 11899.61,4295.28 11312.99,4295.28 v1@10722.44,4295.28 ; 12086.61,7440.94 12086.61,8110.24 v1(12007.87,8188.98) 12007.87,9045.28 11948.82,9104.33 11948.82,9389.76 11899.61,9438.98 11375.98,9438.98 11334.65,9480.32 10744.09,9480.32 v1@10153.54,9480.32 ; v1(8383.86,9480.32) v1(8974.41,9480.31) ; v1(8383.86,9480.32) v1(8974.41,9480.31) ; v1(8383.86,9480.32) v1(8974.41,9480.31) ; v1(8383.86,9480.32) v1(8974.41,9480.31) ; v1(8974.41,9480.31) v1(9564.96,9480.32) ; v1(8974.41,9480.31) v1(9564.96,9480.32) ; v1(8974.41,9480.31) v1(9564.96,9480.32) ; v1(9564.96,9480.32) v1@10153.54,9480.32 ; v1(9564.96,9480.32) v1@10153.54,9480.32 ; v1(10133.86,4295.28) v1@10722.44,4295.28 ; v1(10133.86,4295.28) v1@10722.44,4295.28
  other v2: 9889.76,6452.76 8799.21,6505.91 9889.76,6555.12 8799.21,6594.49 9330.71,6683.07 8799.21,6692.91 9330.71,6820.87 9576.77,6840.55 9655.51,6840.55 9576.77,6938.98 9655.51,6938.98 9330.71,6958.66 9330.71,7096.46 9889.76,7240.16 9889.76,7342.52
  other v3: 10147.64,6850.39 10226.38,6850.39 10147.64,6929.13 10226.38,6929.13
VBAT: C1.2 C2.2 CB1.1 CB2.1 CB3.1 CB4.1 CB5.1 CB6.1 CB7.1 CB8.1 CB9.1 CB10.1 CB11.1 CB12.1 CB13.1 CB14.1 CB15.2 CB18.2 CB19.1 CB20.1 CB21.1 CB22.1 CB23.1 CB24.1 J23.PAD Q1.S Q2.S Q3.S Q4.S Q5.S Q6.S Q7.S Q8.S Q9.S Q10.S Q14.S Q15.S Q16.S Q17.S Q18.S Q19.S Q20.S Q21.S Q22.S Q23.S R22.1 R23.1 R24.1 R25.1 R26.1 R27.1 R28.1 R29.1 R30.1 R31.1 R51.1 R52.1 R53.1 R54.1 R55.1 R56.1 R57.1 R58.1 R59.1 R60.1 R102.2 U1.7 | length 4425.7
  Top Layer w12: 5275.28,5779.83 Q1.S@5334.03,5779.83 ; 5275.59,5885.83 R22.1@5334.65,5885.83 ; 8091.17,7768.34 8091.17,7893.7 Q23.S@8091.17,7999.69 ; 8366.14,7893.7 R55.1@8366.14,7942.91 ; R102.2@8529.53,6299.21 8574.8,6299.21 8598.43,6322.83 ; Q5.S@8582.68,5848.43 8620.26,5886.01 ; 8751.97,7883.86 Q14.S@8751.97,7931.1 Q14.S@8751.97,7935.04 ; 8956.69,7893.7 R56.1@8956.69,7942.91 ; R26.1@8968.5,5836.61 8968.5,5885.83 ; Q6.S@9173.23,5848.43 9173.23,5901.57 ; 9342.52,7883.86 Q15.S@9342.52,7931.1 Q15.S@9342.52,7935.04 ; 9547.24,7893.7 R57.1@9547.24,7942.91 ; R27.1@9559.06,5836.61 9559.06,5885.83 ; Q7.S@9763.78,5848.43 9763.78,5901.57 ; 9933.07,7883.86 Q16.S@9933.07,7931.1 Q16.S@9933.07,7935.04 ; 10137.8,7893.7 R58.1@10137.8,7942.91 ; R28.1@10149.61,5836.61 10149.61,5885.83 ; Q8.S@10354.33,5848.43 10354.33,5901.57 ; 10523.62,7883.86 Q17.S@10523.62,7931.1 Q17.S@10523.62,7935.04 ; 10728.35,7897.64 R59.1@10728.35,7946.85 ; R29.1@10740.16,5836.61 10740.16,5885.83 ; Q9.S@10944.88,5848.43 10944.88,5897.64 ; 11114.17,7883.86 Q18.S@11114.17,7931.1 Q18.S@11114.17,7935.04 ; 11318.9,7893.7 R60.1@11318.9,7942.91 ; R30.1@11330.71,5836.61 11330.71,5885.83 ; Q10.S@11535.43,5848.43 11535.43,5901.57 ; 11622.87,7883.86 11692.91,7883.86 11704.72,7895.67 Q19.S@11704.72,7931.1 Q19.S@11704.72,7935.04 ; R31.1@11921.26,5836.61 11921.26,5885.83
  Top Layer w15: 5728.35,7629.92 5728.35,7736.22 R51.1@5728.35,7893.7 Q20.S@5728.35,7999.69 ; Q2.S@6122.05,5779.53 6122.05,5779.83 R23.1@6122.05,5885.83 6122.05,6043.31 6122.05,6149.61 ; 6515.75,7629.92 R52.1@6515.75,7893.7 ; Q21.S@6515.75,7999.69 Q21.S@6515.75,7992.13 ; Q3.S@6909.45,5779.53 6909.45,5779.83 Q3.S@6909.45,5787.4 ; 6909.45,6149.61 R24.1@6909.45,5885.83 ; 7303.15,7629.92 7303.15,7736.22 R53.1@7303.15,7893.7 Q22.S@7303.15,7999.69 ; Q4.S@7696.85,5779.53 7696.85,5779.83 R25.1@7696.85,5885.83 7696.85,6043.31 7696.85,6149.61 ; R52.1@6515.75,7893.7 Q21.S@6515.75,7992.13 ; R52.1@6515.75,7893.7 Q21.S@6515.75,7992.13 ; Q3.S@6909.45,5787.4 R24.1@6909.45,5885.83 ; Q3.S@6909.45,5787.4 R24.1@6909.45,5885.83
  Top Layer w25: U1.7@11070.87,6527.56 11072.83,6527.56 11122.05,6527.56 11137.8,6543.31 C1.2@11171.26,6543.31 11248.03,6543.31 v1(11248.03,6598.43) ; C1.2@11169.29,6543.31 v1(11169.29,6598.43)
  other v2: 9114.17,5944.88 9704.72,5944.88 10295.28,5944.88 9114.17,6122.05 9704.72,6122.05 10295.28,6122.05 8692.91,6334.65 8692.91,6423.23
pads on no net: U1.2 U1.3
